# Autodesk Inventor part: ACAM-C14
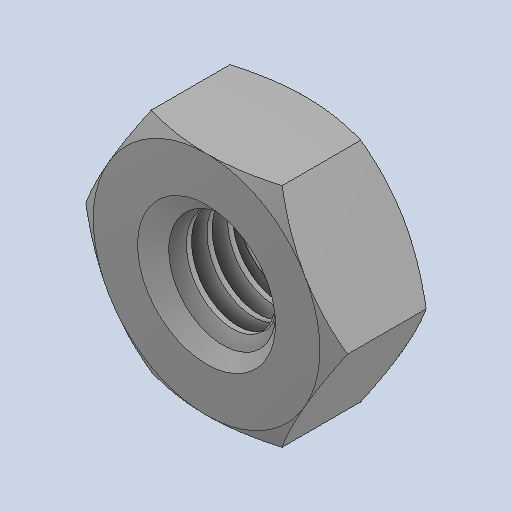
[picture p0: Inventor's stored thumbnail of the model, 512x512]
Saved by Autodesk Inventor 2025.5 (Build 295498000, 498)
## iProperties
Created: 2019-05
Part Number: ACAM-C14
Material: Genérico
Description: Tuerca hexagonal M3
Document SubType Name: Modeling
Designer: Luis M
Density: 1 g/cm^3
Appearance: Valor por defecto
Sending System: SolidWorks 2018
Preprocessor: SwSTEP 2.0
Material_BOM: Por especificar
Proceso_BOM: Comercial
Title: M3 Nut.STEP
Revision Number: HERHANGÝ
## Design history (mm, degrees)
feature "Kes-Süpür1"
node "Sólido1"
